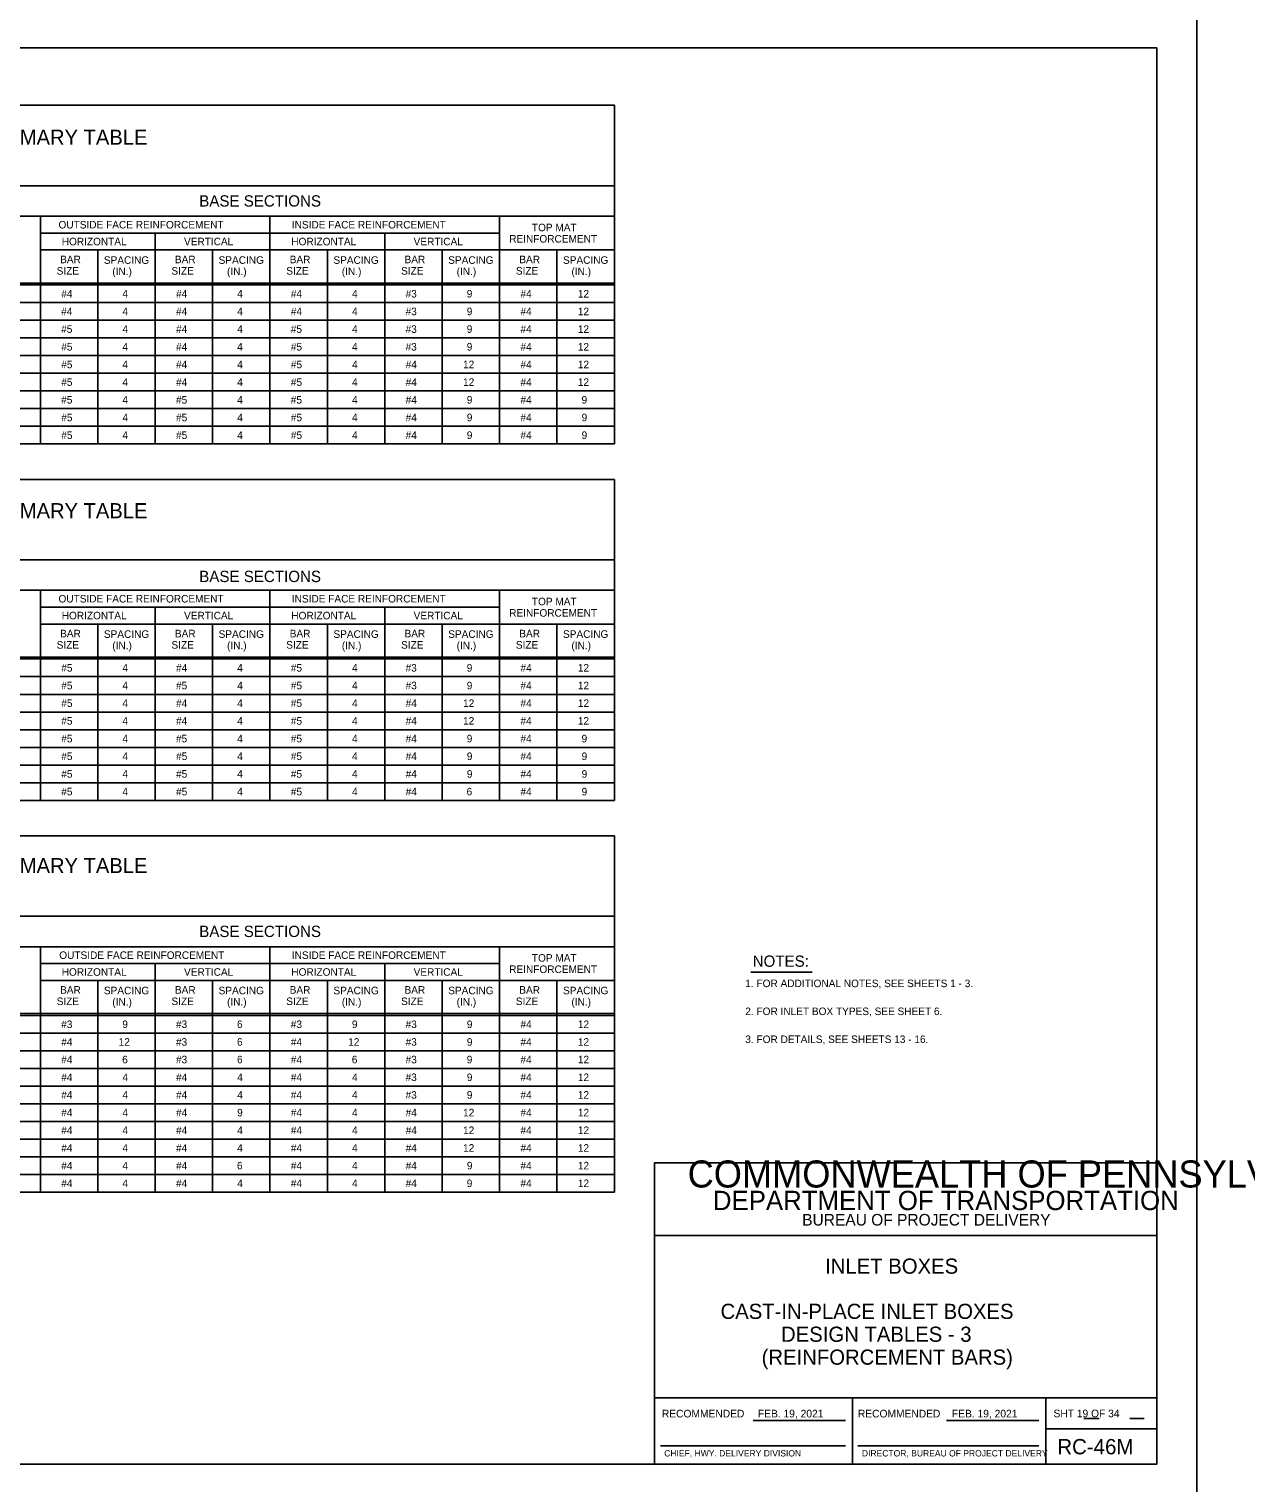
# Model space of a CAD drawing. Extents: x -6420 to 49575, y -4552 to 11624.
# Drawn here: x 331 to 1921, y 3853 to 5753 of the extents above; entities that cross this region are included whole.
import ezdxf

# ---------------------------------------------------------------- set-up
doc = ezdxf.new("R2010")
doc.units = 0
doc.layers.add('1', color=7, linetype='Continuous')
doc.layers.add('PLT-BNDY', color=7, linetype='Continuous')

msp = doc.modelspace()

# ---------------------------------------------------------------- linework, layer by layer
at = {"layer": '1'}
for p, q in [((1096, 5653.2), (-699, 5653.2)), ((1096, 5653.2), (1096, 5210.7)), ((1096, 5548.2), (-699, 5548.2)), ((1096, 5508.2), (-479, 5508.2)), ((346, 5508.2), (346, 5210.7)), ((646, 5508.2), (646, 5210.7)), ((946, 5508.2), (946, 5210.7)), ((346, 5486.2), (646, 5486.2)), ((496, 5486.2), (496, 5210.7)), ((646, 5486.2), (946, 5486.2)), ((796, 5486.2), (796, 5210.7)), ((346, 5464.2), (646, 5464.2)), ((421, 5464.2), (421, 5210.7)), ((571, 5464.2), (571, 5210.7)), ((646, 5464.2), (1096, 5464.2)), ((721, 5464.2), (721, 5210.7)), ((871, 5464.2), (871, 5210.7)), ((1021, 5464.2), (1021, 5210.7)), ((-699, 5421), (1096, 5421)), ((-699, 5418.5), (1096, 5418.5)), ((-699, 5395.4), (1096, 5395.4)), ((-699, 5372.4), (1096, 5372.4)), ((-699, 5349.3), (1096, 5349.3)), ((-699, 5326.2), (1096, 5326.2)), ((-699, 5303.1), (1096, 5303.1)), ((-699, 5280), (1096, 5280)), ((-699, 5256.9), (1096, 5256.9)), ((-699, 5233.8), (1096, 5233.8)), ((-699, 5210.7), (1096, 5210.7)), ((1096, 5164.5), (-699, 5164.5)), ((1096, 5164.5), (1096, 4745)), ((1096, 5059.5), (-699, 5059.5)), ((1096, 5019.5), (-479, 5019.5)), ((346, 5019.5), (346, 4745)), ((646, 5019.5), (646, 4745)), ((946, 5019.5), (946, 4745)), ((346, 4997.5), (646, 4997.5)), ((496, 4997.5), (496, 4745)), ((646, 4997.5), (946, 4997.5)), ((796, 4997.5), (796, 4745)), ((346, 4975.5), (646, 4975.5)), ((421, 4975.5), (421, 4745)), ((571, 4975.5), (571, 4745)), ((646, 4975.5), (1096, 4975.5)), ((721, 4975.5), (721, 4745)), ((871, 4975.5), (871, 4745)), ((1021, 4975.5), (1021, 4745)), ((-699, 4932.2), (1096, 4932.2)), ((-699, 4929.8), (1096, 4929.8)), ((-699, 4906.7), (1096, 4906.7)), ((-699, 4883.6), (1096, 4883.6)), ((-699, 4860.5), (1096, 4860.5)), ((-699, 4837.4), (1096, 4837.4)), ((-699, 4814.3), (1096, 4814.3)), ((-699, 4791.2), (1096, 4791.2)), ((-699, 4768.1), (1096, 4768.1)), ((-699, 4745), (1096, 4745)), ((1096, 4698.8), (-699, 4698.8)), ((1096, 4698.8), (1096, 4233.1)), ((1096, 4593.8), (-699, 4593.8)), ((1096, 4553.8), (-479, 4553.8)), ((346, 4553.8), (346, 4233.1)), ((646, 4553.8), (646, 4233.1)), ((946, 4553.8), (946, 4233.1)), ((346, 4531.8), (646, 4531.8)), ((496, 4531.8), (496, 4233.1)), ((646, 4531.8), (946, 4531.8)), ((796, 4531.8), (796, 4233.1)), ((346, 4509.8), (646, 4509.8)), ((421, 4509.8), (421, 4233.1)), ((571, 4509.8), (571, 4233.1)), ((646, 4509.8), (1096, 4509.8)), ((721, 4509.8), (721, 4233.1)), ((871, 4509.8), (871, 4233.1)), ((1021, 4509.8), (1021, 4233.1)), ((1274.1, 4520.7), (1354.5, 4520.7)), ((-699, 4466.6), (1096, 4466.6)), ((-699, 4464.1), (1096, 4464.1)), ((-699, 4441), (1096, 4441)), ((-699, 4417.9), (1096, 4417.9)), ((-699, 4394.8), (1096, 4394.8)), ((-699, 4371.7), (1096, 4371.7)), ((-699, 4348.6), (1096, 4348.6)), ((-699, 4325.5), (1096, 4325.5)), ((-699, 4302.4), (1096, 4302.4)), ((-699, 4279.3), (1096, 4279.3)), ((-699, 4256.2), (1096, 4256.2)), ((-699, 4233.1), (1096, 4233.1)), ((1277.5, 3934.9), (1397.9, 3934.9)), ((1530.1, 3934.9), (1650.5, 3934.9)), ((1709.2, 3937.5), (1729.4, 3937.5)), ((1769.6, 3937.5), (1788.4, 3937.5)), ((1156.4, 3901.8), (1397.9, 3901.8)), ((1414.1, 3901.8), (1650.5, 3901.8))]:
    msp.add_line(p, q, dxfattribs=at)
msp.add_lwpolyline([(1804.7, 3877.8), (1804.7, 5728.2), (-774, 5728.2), (-774, 3877.8), (1804.7, 3877.8), (1804.7, 3964.3), (1148.5, 3964.3), (1148.5, 4176.5), (1804.7, 4176.5), (1804.7, 4271.5), (1148.5, 4271.5), (1148.5, 3877.8), (1407.1, 3877.8), (1407.1, 3964.3), (1407.1, 3877.8), (1659.7, 3877.8), (1659.7, 3964.3), (1659.7, 3923.9), (1804.7, 3923.9)], dxfattribs=at)
at = {"layer": 'PLT-BNDY'}
msp.add_lwpolyline([(-902, 5777.4), (1857.2, 5777.4), (1857.2, 3828.6), (-902, 3828.6)], close=True, dxfattribs=at)

# ---------------------------------------------------------------- texts
at = {"layer": '1'}
for s, height, p in [('CAST-IN-PLACE CONCRETE INLET BOX SUMMARY TABLE', 19.685, (-246.9, 5601.7)), ('BASE SECTIONS', 14.764, (553.6, 5520.9)), ('OUTSIDE FACE REINFORCEMENT', 9.843, (369.7, 5492.3)), ('INSIDE FACE REINFORCEMENT', 9.843, (674.6, 5492.3)), ('TOP MAT', 9.84, (988.2, 5488.7)), ('HORIZONTAL', 9.84, (373.9, 5470.3)), ('VERTICAL', 9.84, (533.7, 5470.3)), ('HORIZONTAL', 9.84, (673.9, 5470.3)), ('VERTICAL', 9.84, (833.7, 5470.3)), ('REINFORCEMENT', 9.843, (958.6, 5473.9)), ('BAR', 9.84, (371.8, 5446.9)), ('SPACING', 9.84, (429, 5446.1)), ('BAR', 9.84, (521.8, 5446.9)), ('SPACING', 9.84, (578.9, 5446.1)), ('BAR', 9.84, (671.8, 5446.9)), ('SPACING', 9.84, (728.9, 5446.1)), ('BAR', 9.84, (821.8, 5446.9)), ('SPACING', 9.84, (878.9, 5446.1)), ('BAR', 9.84, (971.8, 5446.9)), ('SPACING', 9.84, (1028.9, 5446.1)), ('SIZE', 9.84, (367.3, 5432)), ('(IN.)', 9.84, (440, 5431.3)), ('SIZE', 9.84, (517.3, 5432)), ('(IN.)', 9.84, (589.9, 5431.3)), ('SIZE', 9.84, (667.3, 5432)), ('(IN.)', 9.84, (739.9, 5431.3)), ('SIZE', 9.84, (817.3, 5432)), ('(IN.)', 9.84, (889.9, 5431.3)), ('SIZE', 9.84, (967.3, 5432)), ('(IN.)', 9.84, (1039.9, 5431.3)), ('#4', 9.84, (373.3, 5402.1)), ('4', 9.84, (453.2, 5402.1)), ('#4', 9.84, (523.3, 5402.1)), ('4', 9.84, (603.2, 5402.1)), ('#4', 9.84, (673.3, 5402.1)), ('4', 9.84, (753.2, 5402.1)), ('#3', 9.84, (823.2, 5402.1)), ('9', 9.84, (903.1, 5402.1)), ('#4', 9.84, (973.3, 5402.1)), ('12', 9.84, (1048.3, 5402.1)), ('#4', 9.84, (373.2, 5379)), ('4', 9.84, (453.2, 5379)), ('#4', 9.84, (523.3, 5379)), ('4', 9.84, (603.2, 5379)), ('#4', 9.84, (673.3, 5379)), ('4', 9.84, (753.2, 5379)), ('#3', 9.84, (823.2, 5379)), ('9', 9.84, (903.1, 5379)), ('#4', 9.84, (973.3, 5379)), ('12', 9.84, (1048.3, 5379)), ('#5', 9.84, (373.2, 5355.9)), ('4', 9.84, (453.2, 5355.9)), ('#4', 9.84, (523.3, 5355.9)), ('4', 9.84, (603.2, 5355.9)), ('#5', 9.84, (673.2, 5355.9)), ('4', 9.84, (753.2, 5355.9)), ('#3', 9.84, (823.2, 5355.9)), ('9', 9.84, (903.1, 5355.9)), ('#4', 9.84, (973.3, 5355.9)), ('12', 9.84, (1048.3, 5355.9)), ('#5', 9.84, (373.3, 5332.8)), ('4', 9.84, (453.2, 5332.8)), ('#4', 9.84, (523.3, 5332.8)), ('4', 9.84, (603.2, 5332.8)), ('#5', 9.84, (673.3, 5332.8)), ('4', 9.84, (753.2, 5332.8)), ('#3', 9.84, (823.2, 5332.8)), ('9', 9.84, (903.1, 5332.8)), ('#4', 9.84, (973.3, 5332.8)), ('12', 9.84, (1048.3, 5332.8)), ('#5', 9.84, (373.3, 5309.7)), ('4', 9.84, (453.2, 5309.7)), ('#4', 9.84, (523.3, 5309.7)), ('4', 9.84, (603.2, 5309.7)), ('#5', 9.84, (673.3, 5309.7)), ('4', 9.84, (753.2, 5309.7)), ('#4', 9.84, (823.3, 5309.7)), ('12', 9.84, (898.3, 5309.7)), ('#4', 9.84, (973.3, 5309.7)), ('12', 9.84, (1048.3, 5309.7)), ('#5', 9.84, (373.3, 5286.6)), ('4', 9.84, (453.2, 5286.6)), ('#4', 9.84, (523.3, 5286.6)), ('4', 9.84, (603.2, 5286.6)), ('#5', 9.84, (673.3, 5286.6)), ('4', 9.84, (753.2, 5286.6)), ('#4', 9.84, (823.3, 5286.6)), ('12', 9.84, (898.3, 5286.6)), ('#4', 9.84, (973.3, 5286.6)), ('12', 9.84, (1048.3, 5286.6)), ('#5', 9.84, (373.2, 5263.5)), ('4', 9.84, (453.2, 5263.5)), ('#5', 9.84, (523.2, 5263.5)), ('4', 9.84, (603.2, 5263.5)), ('#5', 9.84, (673.2, 5263.5)), ('4', 9.84, (753.2, 5263.5)), ('#4', 9.84, (823.3, 5263.5)), ('9', 9.84, (903.1, 5263.5)), ('#4', 9.84, (973.3, 5263.5)), ('9', 9.84, (1053.1, 5263.5)), ('#5', 9.84, (373.3, 5240.4)), ('4', 9.84, (453.2, 5240.4)), ('#5', 9.84, (523.3, 5240.4)), ('4', 9.84, (603.2, 5240.4)), ('#5', 9.84, (673.3, 5240.4)), ('4', 9.84, (753.2, 5240.4)), ('#4', 9.84, (823.3, 5240.4)), ('9', 9.84, (903.2, 5240.4)), ('#4', 9.84, (973.3, 5240.4)), ('9', 9.84, (1053.2, 5240.4)), ('#5', 9.84, (373.3, 5217.3)), ('4', 9.84, (453.2, 5217.3)), ('#5', 9.84, (523.3, 5217.3)), ('4', 9.84, (603.2, 5217.3)), ('#5', 9.84, (673.3, 5217.3)), ('4', 9.84, (753.2, 5217.3)), ('#4', 9.84, (823.3, 5217.3)), ('9', 9.84, (903.2, 5217.3)), ('#4', 9.84, (973.3, 5217.3)), ('9', 9.84, (1053.2, 5217.3)), ('CAST-IN-PLACE CONCRETE INLET BOX SUMMARY TABLE', 19.685, (-246.9, 5113.7)), ('BASE SECTIONS', 14.764, (553.6, 5030.3)), ('OUTSIDE FACE REINFORCEMENT', 9.843, (369.7, 5003.6)), ('INSIDE FACE REINFORCEMENT', 9.843, (674.6, 5003.6)), ('TOP MAT', 9.84, (988.2, 5000)), ('HORIZONTAL', 9.84, (373.9, 4981.6)), ('VERTICAL', 9.84, (533.7, 4981.6)), ('HORIZONTAL', 9.84, (673.9, 4981.6)), ('VERTICAL', 9.84, (833.7, 4981.6)), ('REINFORCEMENT', 9.843, (958.6, 4985.1)), ('BAR', 9.84, (371.8, 4958.1)), ('SPACING', 9.84, (429, 4957.4)), ('BAR', 9.84, (521.8, 4958.1)), ('SPACING', 9.84, (578.9, 4957.4)), ('BAR', 9.84, (671.8, 4958.1)), ('SPACING', 9.84, (728.9, 4957.4)), ('BAR', 9.84, (821.8, 4958.1)), ('SPACING', 9.84, (878.9, 4957.4)), ('BAR', 9.84, (971.8, 4958.1)), ('SPACING', 9.84, (1028.9, 4957.4)), ('SIZE', 9.84, (367.3, 4943.3)), ('(IN.)', 9.84, (440, 4942.5)), ('SIZE', 9.84, (517.3, 4943.3)), ('(IN.)', 9.84, (589.9, 4942.5)), ('SIZE', 9.84, (667.3, 4943.3)), ('(IN.)', 9.84, (739.9, 4942.5)), ('SIZE', 9.84, (817.3, 4943.3)), ('(IN.)', 9.84, (889.9, 4942.5)), ('SIZE', 9.84, (967.3, 4943.3)), ('(IN.)', 9.84, (1039.9, 4942.5)), ('#5', 9.84, (373.3, 4913.3)), ('4', 9.84, (453.2, 4913.3)), ('#4', 9.84, (523.3, 4913.3)), ('4', 9.84, (603.2, 4913.3)), ('#5', 9.84, (673.3, 4913.3)), ('4', 9.84, (753.2, 4913.3)), ('#3', 9.84, (823.2, 4913.3)), ('9', 9.84, (903.1, 4913.3)), ('#4', 9.84, (973.3, 4913.3)), ('12', 9.84, (1048.3, 4913.3)), ('#5', 9.84, (373.3, 4890.2)), ('4', 9.84, (453.2, 4890.2)), ('#5', 9.84, (523.2, 4890.2)), ('4', 9.84, (603.2, 4890.2)), ('#5', 9.84, (673.3, 4890.2)), ('4', 9.84, (753.2, 4890.2)), ('#3', 9.84, (823.2, 4890.2)), ('9', 9.84, (903.1, 4890.2)), ('#4', 9.84, (973.3, 4890.2)), ('12', 9.84, (1048.3, 4890.2)), ('#5', 9.84, (373.3, 4867.1)), ('4', 9.84, (453.2, 4867.1)), ('#4', 9.84, (523.3, 4867.1)), ('4', 9.84, (603.2, 4867.1)), ('#5', 9.84, (673.3, 4867.1)), ('4', 9.84, (753.2, 4867.1)), ('#4', 9.84, (823.3, 4867.1)), ('12', 9.84, (898.3, 4867.1)), ('#4', 9.84, (973.3, 4867.1)), ('12', 9.84, (1048.3, 4867.1)), ('#5', 9.84, (373.3, 4844)), ('4', 9.84, (453.2, 4844)), ('#4', 9.84, (523.3, 4844)), ('4', 9.84, (603.2, 4844)), ('#5', 9.84, (673.3, 4844)), ('4', 9.84, (753.2, 4844)), ('#4', 9.84, (823.3, 4844)), ('12', 9.84, (898.3, 4844)), ('#4', 9.84, (973.3, 4844)), ('12', 9.84, (1048.3, 4844)), ('#5', 9.84, (373.3, 4820.9)), ('4', 9.84, (453.2, 4820.9)), ('#5', 9.84, (523.2, 4820.9)), ('4', 9.84, (603.2, 4820.9)), ('#5', 9.84, (673.3, 4820.9)), ('4', 9.84, (753.2, 4820.9)), ('#4', 9.84, (823.3, 4820.9)), ('9', 9.84, (903.1, 4820.9)), ('#4', 9.84, (973.3, 4820.9)), ('9', 9.84, (1053.1, 4820.9)), ('#5', 9.84, (373.3, 4797.8)), ('4', 9.84, (453.2, 4797.8)), ('#5', 9.84, (523.3, 4797.8)), ('4', 9.84, (603.2, 4797.8)), ('#5', 9.84, (673.3, 4797.8)), ('4', 9.84, (753.2, 4797.8)), ('#4', 9.84, (823.3, 4797.8)), ('9', 9.84, (903.2, 4797.8)), ('#4', 9.84, (973.3, 4797.8)), ('9', 9.84, (1053.2, 4797.8)), ('#5', 9.84, (373.3, 4774.7)), ('4', 9.84, (453.2, 4774.7)), ('#5', 9.84, (523.3, 4774.7)), ('4', 9.84, (603.2, 4774.7)), ('#5', 9.84, (673.3, 4774.7)), ('4', 9.84, (753.2, 4774.7)), ('#4', 9.84, (823.3, 4774.7)), ('9', 9.84, (903.2, 4774.7)), ('#4', 9.84, (973.3, 4774.7)), ('9', 9.84, (1053.2, 4774.7)), ('#5', 9.84, (373.3, 4751.6)), ('4', 9.84, (453.2, 4751.6)), ('#5', 9.84, (523.3, 4751.6)), ('4', 9.84, (603.2, 4751.6)), ('#5', 9.84, (673.3, 4751.6)), ('4', 9.84, (753.2, 4751.6)), ('#4', 9.84, (823.3, 4751.6)), ('6', 9.84, (902.9, 4751.6)), ('#4', 9.84, (973.3, 4751.6)), ('9', 9.84, (1053.2, 4751.6)), ('CAST-IN-PLACE CONCRETE INLET BOX SUMMARY TABLE', 19.685, (-246.9, 4650)), ('BASE SECTIONS', 14.764, (553.6, 4566.5)), ('OUTSIDE FACE REINFORCEMENT', 9.843, (370.7, 4537.9)), ('INSIDE FACE REINFORCEMENT', 9.843, (674.6, 4537.9)), ('TOP MAT', 9.84, (988.2, 4534.3)), ('NOTES:', 14.76, (1276.7, 4527.6)), ('HORIZONTAL', 9.84, (373.9, 4515.9)), ('VERTICAL', 9.84, (533.7, 4515.9)), ('HORIZONTAL', 9.84, (673.9, 4515.9)), ('VERTICAL', 9.84, (833.7, 4515.9)), ('REINFORCEMENT', 9.843, (958.6, 4519.5)), ('BAR', 9.84, (371.8, 4492.5)), ('BAR', 9.84, (521.8, 4492.5)), ('BAR', 9.84, (671.8, 4492.5)), ('BAR', 9.84, (821.8, 4492.5)), ('BAR', 9.84, (971.8, 4492.5)), (' 1. FOR ADDITIONAL NOTES, SEE SHEETS 1 - 3.', 9.843, (1263.4, 4501)), ('SIZE', 9.84, (367.3, 4477.6)), ('SPACING', 9.84, (429, 4491.7)), ('(IN.)', 9.84, (440, 4476.9)), ('SIZE', 9.84, (517.3, 4477.6)), ('SPACING', 9.84, (578.9, 4491.7)), ('(IN.)', 9.84, (589.9, 4476.9)), ('SIZE', 9.84, (667.3, 4477.6)), ('SPACING', 9.84, (728.9, 4491.7)), ('(IN.)', 9.84, (739.9, 4476.9)), ('SIZE', 9.84, (817.3, 4477.6)), ('SPACING', 9.84, (878.9, 4491.7)), ('(IN.)', 9.84, (889.9, 4476.9)), ('SIZE', 9.84, (967.3, 4477.6)), ('SPACING', 9.84, (1028.9, 4491.7)), ('(IN.)', 9.84, (1039.9, 4476.9)), (' 2. FOR INLET BOX TYPES, SEE SHEET 6.', 9.843, (1263.4, 4464.5)), ('#3', 9.84, (373.2, 4447.6)), ('9', 9.84, (453.1, 4447.6)), ('#3', 9.84, (523.2, 4447.6)), ('6', 9.84, (602.9, 4447.6)), ('#3', 9.84, (673.2, 4447.6)), ('9', 9.84, (753.1, 4447.6)), ('#3', 9.84, (823.2, 4447.6)), ('9', 9.84, (903.2, 4447.6)), ('#4', 9.84, (973.3, 4447.6)), ('12', 9.84, (1048.3, 4447.6)), ('#4', 9.84, (373.3, 4424.5)), ('12', 9.84, (448.3, 4424.5)), ('#3', 9.84, (523.2, 4424.5)), ('6', 9.84, (602.9, 4424.5)), ('#4', 9.84, (673.3, 4424.5)), ('12', 9.84, (748.3, 4424.5)), ('#3', 9.84, (823.2, 4424.5)), ('9', 9.84, (903.2, 4424.5)), ('#4', 9.84, (973.3, 4424.5)), ('12', 9.84, (1048.3, 4424.5)), (' 3. FOR DETAILS, SEE SHEETS 13 - 16.', 9.843, (1263.4, 4428)), ('#4', 9.84, (373.3, 4401.5)), ('6', 9.84, (452.9, 4401.5)), ('#3', 9.84, (523.2, 4401.5)), ('6', 9.84, (602.9, 4401.5)), ('#4', 9.84, (673.3, 4401.5)), ('6', 9.84, (752.9, 4401.5)), ('#3', 9.84, (823.2, 4401.5)), ('9', 9.84, (903.1, 4401.5)), ('#4', 9.84, (973.3, 4401.5)), ('12', 9.84, (1048.3, 4401.5)), ('#4', 9.84, (373.3, 4378.3)), ('4', 9.84, (453.2, 4378.3)), ('#4', 9.84, (523.3, 4378.3)), ('4', 9.84, (603.2, 4378.3)), ('#4', 9.84, (673.3, 4378.3)), ('4', 9.84, (753.2, 4378.3)), ('#3', 9.84, (823.2, 4378.3)), ('9', 9.84, (903.2, 4378.3)), ('#4', 9.84, (973.3, 4378.3)), ('12', 9.84, (1048.3, 4378.3)), ('#4', 9.84, (373.3, 4355.3)), ('4', 9.84, (453.2, 4355.3)), ('#4', 9.84, (523.3, 4355.3)), ('4', 9.84, (603.2, 4355.3)), ('#4', 9.84, (673.3, 4355.3)), ('4', 9.84, (753.2, 4355.3)), ('#3', 9.84, (823.2, 4355.3)), ('9', 9.84, (903.2, 4355.3)), ('#4', 9.84, (973.3, 4355.3)), ('12', 9.84, (1048.3, 4355.3)), ('#4', 9.84, (373.3, 4332.2)), ('4', 9.84, (453.2, 4332.2)), ('#4', 9.84, (523.3, 4332.2)), ('9', 9.84, (603.1, 4332.2)), ('#4', 9.84, (673.3, 4332.2)), ('4', 9.84, (753.2, 4332.2)), ('#4', 9.84, (823.3, 4332.2)), ('12', 9.84, (898.3, 4332.2)), ('#4', 9.84, (973.3, 4332.2)), ('12', 9.84, (1048.3, 4332.2)), ('#4', 9.84, (373.3, 4309.1)), ('4', 9.84, (453.2, 4309.1)), ('#4', 9.84, (523.3, 4309.1)), ('4', 9.84, (603.2, 4309.1)), ('#4', 9.84, (673.3, 4309.1)), ('4', 9.84, (753.2, 4309.1)), ('#4', 9.84, (823.3, 4309.1)), ('12', 9.84, (898.3, 4309.1)), ('#4', 9.84, (973.3, 4309.1)), ('12', 9.84, (1048.3, 4309.1)), ('#4', 9.84, (373.3, 4286)), ('4', 9.84, (453.2, 4286)), ('#4', 9.84, (523.3, 4286)), ('4', 9.84, (603.2, 4286)), ('#4', 9.84, (673.3, 4286)), ('4', 9.84, (753.2, 4286)), ('#4', 9.84, (823.3, 4286)), ('12', 9.84, (898.3, 4286)), ('#4', 9.84, (973.3, 4286)), ('12', 9.84, (1048.3, 4286)), ('COMMONWEALTH OF PENNSYLVANIA', 35.379, (1191.7, 4239.2)), ('#4', 9.84, (373.3, 4262.9)), ('4', 9.84, (453.2, 4262.9)), ('#4', 9.84, (523.3, 4262.9)), ('6', 9.84, (602.9, 4262.9)), ('#4', 9.84, (673.3, 4262.9)), ('4', 9.84, (753.2, 4262.9)), ('#4', 9.84, (823.3, 4262.9)), ('9', 9.84, (903.2, 4262.9)), ('#4', 9.84, (973.3, 4262.9)), ('12', 9.84, (1048.3, 4262.9)), ('#4', 9.84, (373.3, 4239.8)), ('4', 9.84, (453.2, 4239.8)), ('#4', 9.84, (523.3, 4239.8)), ('4', 9.84, (603.2, 4239.8)), ('#4', 9.84, (673.3, 4239.8)), ('4', 9.84, (753.2, 4239.8)), ('#4', 9.84, (823.3, 4239.8)), ('9', 9.84, (903.1, 4239.8)), ('#4', 9.84, (973.3, 4239.8)), ('12', 9.84, (1048.3, 4239.8)), ('DEPARTMENT OF TRANSPORTATION', 25.211, (1224.7, 4209.7)), ('BUREAU OF PROJECT DELIVERY', 15.164, (1341.4, 4189.5)), ('INLET BOXES', 19.816, (1371.4, 4126.6)), ('CAST-IN-PLACE INLET BOXES', 19.816, (1234.7, 4067.5)), ('DESIGN TABLES - 3', 19.816, (1313.8, 4037.6)), ('(REINFORCEMENT BARS)', 19.816, (1288.4, 4007.7)), ('RECOMMENDED', 10, (1158.1, 3938.8)), ('FEB. 19, 2021', 10, (1283.6, 3938.8)), ('RECOMMENDED', 10, (1414.2, 3938.8)), ('FEB. 19, 2021', 10, (1537.1, 3938.8)), ('SHT 19 OF 34', 10, (1669.8, 3939)), ('CHIEF, HWY. DELIVERY DIVISION', 8.333, (1161.1, 3887.8)), ('DIRECTOR, BUREAU OF PROJECT DELIVERY', 8.333, (1419.4, 3887.8)), ('RC-46M', 20, (1674.7, 3890.6))]:
    msp.add_text(s, height=height, dxfattribs=at).set_placement(p)

doc.saveas('drawing.dxf')
